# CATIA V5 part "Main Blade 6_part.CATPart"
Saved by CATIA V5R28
Part number: Main Blade 6_part
Definition: design
Nomenclature: Main Blade 6_part
Source: Unknown
Bounding box of the stored display mesh (mm): x -4.967 to -0.177, y -1.801 to 10.09, z 1.529 to 7.748
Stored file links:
  D:\paraturbo-cad\STEP\Turbocompressor_for_Christophe\Main Blade 6_part.CATPart
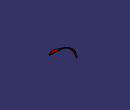
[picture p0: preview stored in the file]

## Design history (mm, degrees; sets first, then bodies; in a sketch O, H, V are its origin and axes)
Body1 "MANIFOLD_SOLID_BREP #47045" (main body)
  Solid1: solid without history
